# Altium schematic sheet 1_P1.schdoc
size 429 x 307 mm; Symbol: Drawing-Symbol_A4; Device: Drawing-Symbol_A4; @Project Name: HSSM-Prog; @Page Count: 1; @Update Date: 2025-03-10; @Create Date: 2025-01-19; @Schematic Name: Schematic1; @Page No: 1; @Page Name: P1; Company: EasyEDA.com; Version: V1.0; Page Size: A4; @Create Time: 21:43:06; @Update Time: 07:12:20; Width: 1655; Height: 1170; Region Start: 1; X Region Count: 6; Y Region Count: 4; Blade Width: 10; Title Block Position: 3; @Board Name: Board1
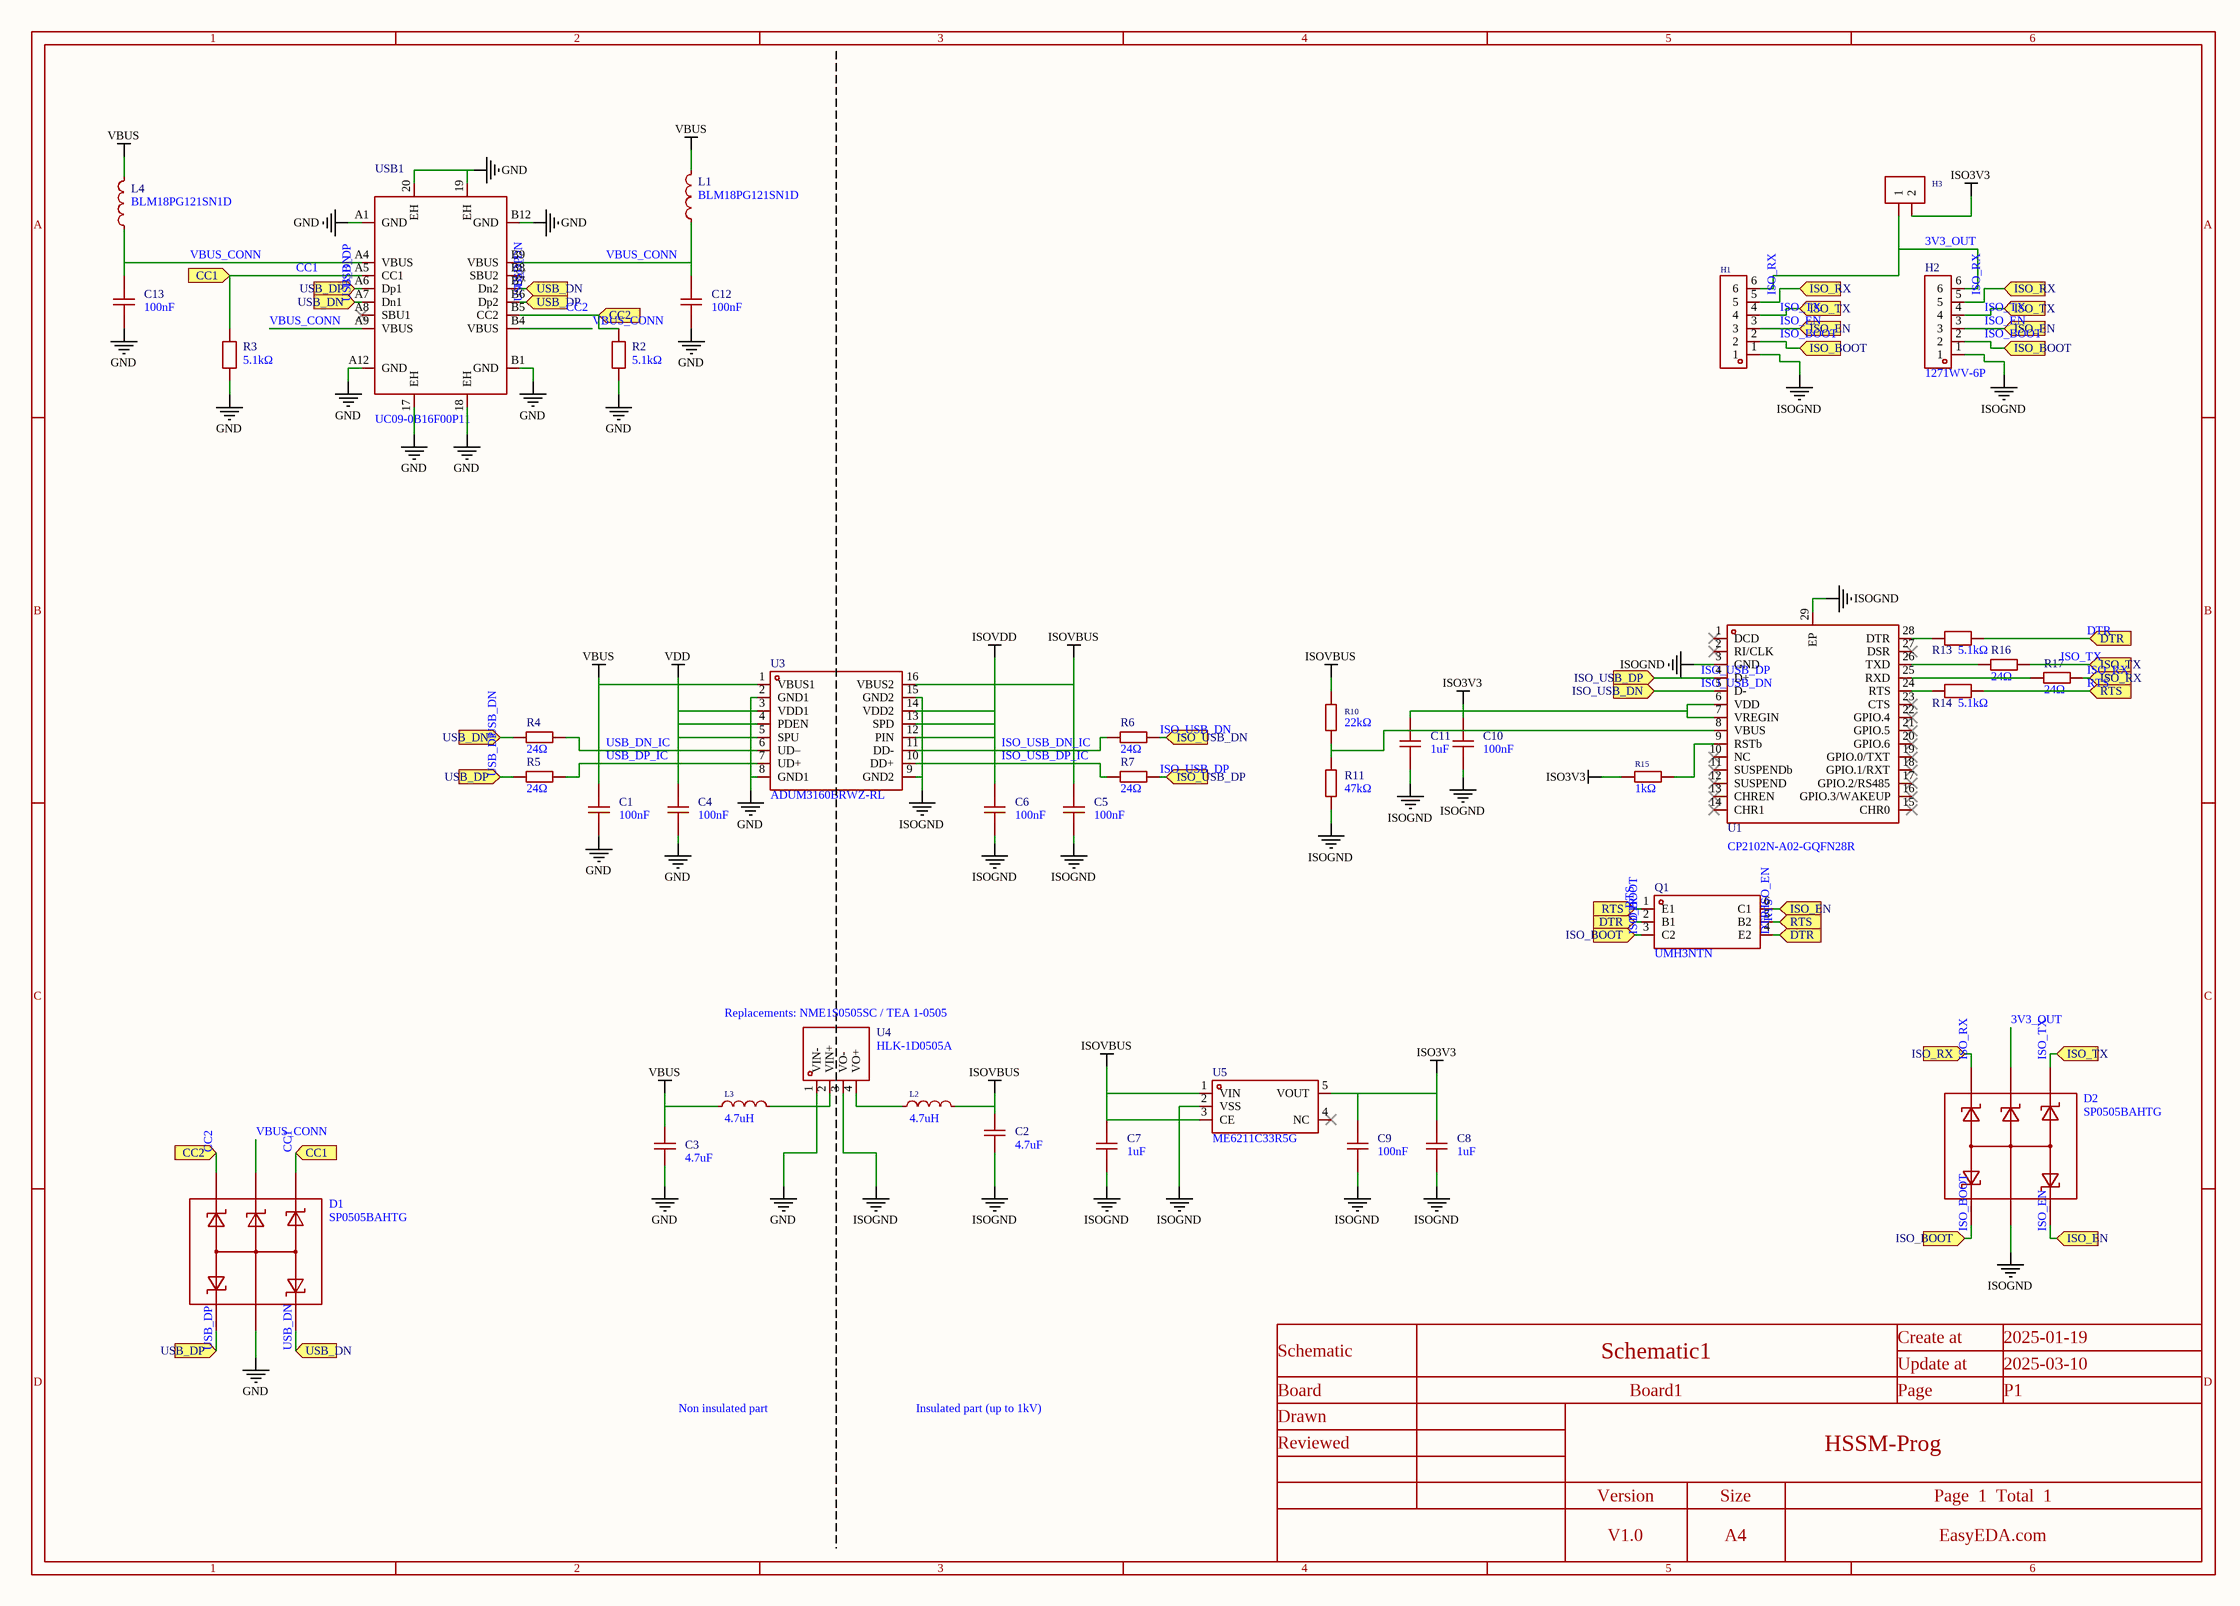
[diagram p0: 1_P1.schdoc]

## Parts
C1  100nF  [C0402]
C2  4.7uF  [C0603]
C3  4.7uF  [C0603]
C4  100nF  [C0402]
C5  100nF  [C0402]
C6  100nF  [C0402]
C7  1uF  [C0402]
C8  1uF  [C0402]
C9  100nF  [C0402]
C10  100nF  [C0402]
C11  1uF  [C0402]
C12  100nF  [C0402]
C13  100nF  [C0402]
D1  SP0505BAHTG  [SOT-23-6_L2.9-W1.6-P0.95-LS2.8-BR]
D2  SP0505BAHTG  [SOT-23-6_L2.9-W1.6-P0.95-LS2.8-BR]
H1  (no value)  [HDR-TH_6P-P2.54-V-F]
H2  1271WV-6P  [HDR-TH_6P-P1.27-V-M-A]
H3  (no value)  [HDR-TH_2P-P2.54-V-F]
L1  BLM18PG121SN1D  [L0603]
L2  4.7uH  [IND-SMD_L4.0-W4.0_SMNR4020]
L3  4.7uH  [IND-SMD_L4.0-W4.0_SMNR4020]
L4  BLM18PG121SN1D  [L0603]
Q1  UMH3NTN  [SOT-363_L2.0-W1.3-P0.65-LS2.1-TL]
R2  5.1kΩ  [R0402]
R3  5.1kΩ  [R0402]
R4  24Ω  [R0402]
R5  24Ω  [R0402]
R6  24Ω  [R0402]
R7  24Ω  [R0402]
R10  22kΩ  [R0402]
R11  47kΩ  [R0402]
R13  5.1kΩ  [R0402]
R14  5.1kΩ  [R0402]
R15  1kΩ  [R0402]
R16  24Ω  [R0402]
R17  24Ω  [R0402]
U1  CP2102N-A02-GQFN28R  [QFN-28_L5.0-W5.0-P0.50-TL-EP3.3]
U3  ADUM3160BRWZ-RL  [SOIC-16_L10.3-W7.5-P1.27-LS10.3-BL]
U4  HLK-1D0505A  [PWRM-TH_HLK-1DXXXX]
U5  ME6211C33R5G  [SOT-353_L2.1-W1.3-P0.65-LS2.3-BL]
USB1  UC09-0B16F00P11  [USB-C_UC09-0B16F00P11]

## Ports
CC1 (in), CC2 (in), DTR (in), ISO_BOOT (in), ISO_EN (in), ISO_RX (in), ISO_TX (in), ISO_USB_DN (in), ISO_USB_DP (in), RTS (in), USB_DN (in), USB_DP (in)

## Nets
GND: C1.1 C3.1 C4.1 C12.1 C13.1 D1.2 R2.1 R3.1 U3.2(GND1) U3.8(GND1) U4.1(VIN-) USB1.17(EH) USB1.18(EH) USB1.19(EH) USB1.20(EH) USB1.A1(GND) USB1.A12(GND) USB1.B1(GND) USB1.B12(GND)
ISO3V3: C8.2 C9.2 C10.2 C11.2 H3.2 R15.1 U1.6(VDD) U1.7(VREGIN) U5.5(VOUT)
ISOGND: C2.1 C5.1 C6.1 C7.1 C8.1 C9.1 C10.1 C11.1 D2.2 H1.1 H2.1 R11.1 U1.3(GND) U1.29(EP) U3.9(GND2) U3.15(GND2) U4.3(VO-) U5.2(VSS)
ISOVBUS: C2.2 C5.2 C7.2 L2.1 R10.2 U3.16(VBUS2) U5.1(VIN) U5.3(CE)
ISOVDD: C6.2 U3.12(PIN) U3.13(SPD) U3.14(VDD2)
VBUS: C1.2 C3.2 L1.2 L3.2 L4.2 U3.1(VBUS1)
VDD: C4.2 U3.3(VDD1) U3.4(PDEN) U3.5(SPU)
3V3_OUT: D2.5 H1.6 H2.6 H3.1
CC1: D1.4 R3.2 USB1.A5(CC1) ; port CC1
CC2: D1.6 R2.2 USB1.B5(CC2) ; port CC2
DTR: Q1.2(B1) Q1.4(E2) R13.1 ; port DTR
ISO_BOOT: D2.1 H1.2 H2.2 Q1.3(C2) ; port ISO_BOOT
ISO_EN: D2.3 H1.3 H2.3 Q1.6(C1) ; port ISO_EN
ISO_RX: D2.6 H1.5 H2.5 R17.2 ; port ISO_RX
ISO_TX: D2.4 H1.4 H2.4 R16.2 ; port ISO_TX
ISO_USB_DN: R6.2 U1.5(D-) ; port ISO_USB_DN
ISO_USB_DN_IC: R6.1 U3.11(DD-)
ISO_USB_DP: R7.2 U1.4(D+) ; port ISO_USB_DP
ISO_USB_DP_IC: R7.1 U3.10(DD+)
RTS: Q1.1(E1) Q1.5(B2) R14.1 ; port RTS
USB_DN: D1.3 R4.1 USB1.A7(Dn1) USB1.B7(Dn2) ; port USB_DN
USB_DN_IC: R4.2 U3.6(UD–)
USB_DP: D1.1 R5.1 USB1.A6(Dp1) USB1.B6(Dp2) ; port USB_DP
USB_DP_IC: R5.2 U3.7(UD+)
VBUS_CONN: C12.2 C13.2 D1.5 L1.1 L4.1 USB1.A4(VBUS) USB1.A9(VBUS) USB1.B4(VBUS) USB1.B9(VBUS)
NetL2_2: L2.2 U4.4(VO+)
NetL3_1: L3.1 U4.2(VIN+)
NetR10_1: R10.1 R11.2 U1.8(VBUS)
NetR13_2: R13.2 U1.28(DTR)
NetR14_2: R14.2 U1.24(RTS)
NetR15_2: R15.2 U1.9(RSTb)
NetR16_1: R16.1 U1.26(TXD)
NetR17_1: R17.1 U1.25(RXD)

Not connected (* = marked no-connect by the designer): U1 1(DCD)* 2(RI/CLK)* 10(NC)* 11(SUSPENDb)* 12(SUSPEND)* 13(CHREN)* 14(CHR1)* 15(CHR0)* 16(GPIO.3/WAKEUP)* 17(GPIO.2/RS485)* 18(GPIO.1/RXT)* 19(GPIO.0/TXT)* 20(GPIO.6)* 21(GPIO.5)* 22(GPIO.4)* 23(CTS)* 27(DSR)*; U5 4(NC)*; USB1 A8(SBU1)* B8(SBU2)*

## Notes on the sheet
- Replacements: NME1S0505SC / TEA 1-0505
- Non insulated part
- Insulated part (up to 1kV)

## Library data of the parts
C1 C4-C6 C9 C10 C12 C13 = CL05B104KO5NNNC: Manufacturer: SAMSUNG(三星); Add into BOM: yes; Tolerance: ±10%
C2 C3 = CL10A475KO8NNNC: Manufacturer: SAMSUNG(三星); Add into BOM: yes; Tolerance: ±10%
C7 C8 C11 = CL05A105KA5NQNC: Manufacturer: SAMSUNG(三星); Add into BOM: yes; Tolerance: ±10%
D1 D2 = SP0505BAHTG: Manufacturer: Littelfuse(美国力特); Add into BOM: yes; polarity: Unidirectional; Reverse Stand-Off Voltage (Vrwm): 5.5V@Max; Maximum Clamping Voltage: 8.5V; Type: TVS
H1 = HDR-F_2.54_1x6P: Manufacturer: BOOMELE(博穆精密); Manufacturer Part: 2.54-1*6P母; Symbol: Header-Female-2.54_1x6; Convert to PCB: yes
H2 = 1271WV-6P: Manufacturer: HanElectricity(瀚源); Add into BOM: yes; Pin Structure: 1x6P; Pitch: 1.27mm; Circluar Pins/Square Pins: Square Pins
H3 = HDR-F_2.54_1x2P: Manufacturer: BOOMELE(博穆精密); Manufacturer Part: 2.54-1*2P母; Symbol: Header-Female-2.54_1x2; Convert to PCB: yes
L1 L4 = BLM18PG121SN1D_C14709: Manufacturer: muRata(村田); Add into BOM: yes; Impedance @ Frequency: 120Ω@100MHz; Tolerance: ±25%; DC Resistance: 50mΩ; Current Rating: 2A; Circuits: 1
L2 L3 = FNR4012S4R7MT: Manufacturer: cjiang(长江微电); Add into BOM: yes; Tolerance: ±20%; Saturation Current (Isat): 1.8A; DC Resistance (DCR): 163mΩ
Q1 = UMH3NTN: Manufacturer: ROHM(罗姆); Add into BOM: yes; Collector-Emitter Breakdown Voltage (Vceo): 50V; Collector Current (Ic): 100mA; Power Dissipation (Pd): 150mW; DC Current Gain (hFE@Ic,Vce): 100@1mA,5V; Input Resistor: 6.11kΩ
R2 R3 R13 R14 = RCA025K1JLF: Manufacturer: HKR(香港电阻); Add into BOM: yes; Tolerance: ±5%
R4-R7 R16 R17 = AC0402FR-0724RL: Manufacturer: YAGEO(国巨); Add into BOM: yes; Tolerance: ±1%; Temperature Coefficient: ±100ppm/℃
R10 = 0402WGF2202TCE: Manufacturer: UNI-ROYAL(厚声); Add into BOM: yes; Tolerance: ±1%; Temperature Coefficient: ±100ppm/℃
R11 = 0402WGF4702TCE: Manufacturer: UNI-ROYAL(厚声); Add into BOM: yes; Tolerance: ±1%; Temperature Coefficient: ±100ppm/℃
R15 = 0402WGF1001TCE: Manufacturer: UNI-ROYAL(厚声); Add into BOM: yes; Tolerance: ±1%; Temperature Coefficient: ±100ppm/℃
U1 = CP2102N-A02-GQFN28R: Manufacturer: SKYWORKS/SILICON LABS(芯科); Add into BOM: yes; Applications Function: USB to UART; Supply Voltage: 3V~3.6V
U3 = ADUM3160BRWZ-RL: Manufacturer: ADI(亚德诺); Add into BOM: yes
U4 = HLK-1D0505A: Manufacturer: HI-LINK(海凌科); Add into BOM: yes
U5 = ME6211C33R5G: Manufacturer: MICRONE(南京微盟); Add into BOM: yes; Maximum Input Voltage: 6.5V; Output Voltage: 3.3V; MAX Output Current: 300mA; Power Supply Rejection Ratio (PSRR): 70dB@(1kHz); Dropout Voltage: 260mV@(200mA); Output Polarity: Positive electrode; Number of Outputs: 1
USB1 = UC09-0B16F00P11: Manufacturer: BXCONN(宝讯); Add into BOM: yes; Connector Type: Type-C; Gender: Female; Number of Contacts: 16P; Number of Ports: 1; Current Rating - Power (Max): 3A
